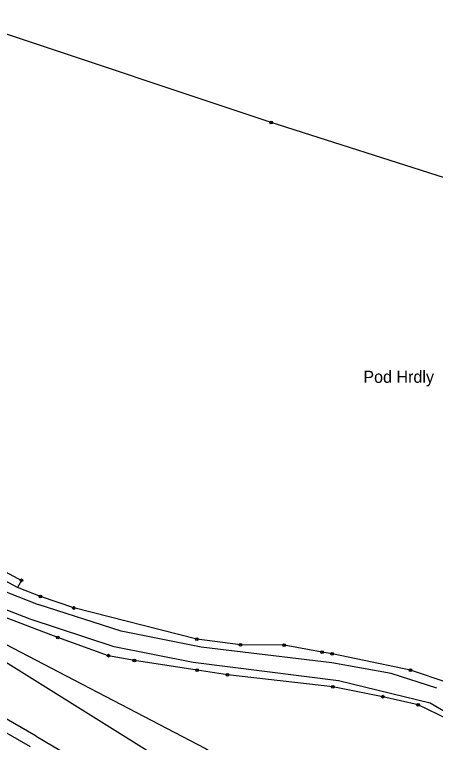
# Model space of a CAD drawing. Extents: x -758582 to -751794, y -998770 to -994350.
# Drawn here: x -754610.6 to -754456.7, y -996434.2 to -996167.7 of the extents above; entities that cross this region are included whole.
import ezdxf

# ---------------------------------------------------------------- set-up
doc = ezdxf.new("R2010")
doc.units = 0
for name, color, linetype in [('Hranice parcel', 7, 'Continuous'), ('Pop  PČ popisy', 7, 'Continuous'), ('Poz předměty', 7, 'Continuous'), ('Vnitřní kresba', 7, 'Continuous'), ('Značky bodu BP', 7, 'Continuous')]:
    doc.layers.add(name, color=color, linetype=linetype)

msp = doc.modelspace()

# ---------------------------------------------------------------- linework, layer by layer
at = {"layer": 'Hranice parcel'}
for points in [[(-754788.86, -996300.01), (-754785.16, -996301.49), (-754719.09, -996332.73), (-754690.11, -996345.48), (-754674.83, -996351.49), (-754634.95, -996361.65), (-754625.47, -996365.55), (-754608.08, -996374.84), (-754609.52, -996377.47)], [(-754609.52, -996377.47), (-754626.61, -996368.32), (-754626.93, -996368.19)], [(-754383.69, -996482.57), (-754386.49, -996481.22), (-754395.83, -996466.38), (-754410.6, -996446.84), (-754437.49, -996420.56), (-754451.97, -996412.36), (-754465.76, -996407.75), (-754494.47, -996401.74), (-754498.09, -996401.1), (-754512, -996398.53), (-754527.95, -996398.42), (-754543.94, -996396.33), (-754588.89, -996384.95), (-754601.1, -996380.73), (-754609.52, -996377.47)], [(-754380.19, -996552.13), (-754385.25, -996519.98), (-754387.72, -996506.25), (-754392.07, -996496.35), (-754394.77, -996491.32), (-754402.71, -996478.9), (-754429.39, -996448.06), (-754441.07, -996434.06), (-754445.75, -996429.16), (-754451.91, -996425.8), (-754462.97, -996420.4), (-754475.9, -996417.42), (-754494.23, -996413.79), (-754532.74, -996409.39), (-754543.79, -996407.71), (-754566.79, -996404.2), (-754576.27, -996402.41), (-754594.78, -996395.73), (-754627.79, -996383.24)], [(-754630.89, -996386.93), (-754622.69, -996393.73), (-754540.76, -996436.36), (-754489.08, -996468.96), (-754461.34, -996488.31), (-754439.14, -996506.23), (-754383.88, -996547.82), (-754380.19, -996552.13)], [(-754376, -996565.84), (-754445.23, -996512.86), (-754489.02, -996482.87), (-754618.93, -996401.76), (-754635.21, -996396.28), (-754637.74, -996394.86)]]:
    msp.add_lwpolyline(points, dxfattribs=at)
at = {"layer": 'Poz předměty'}
for p, q in [((-754516.72, -996207.25), (-754635.04, -996167.71)), ((-754397.31, -996245.46), (-754516.72, -996207.25)), ((-754602.64, -996431.86), (-754633.76, -996414.06)), ((-754604.81, -996435.76), (-754635.9, -996417.94)), ((-754602.64, -996431.86), (-754577.74, -996446.58))]:
    msp.add_line(p, q, dxfattribs=at)
for radius in [0.5, 0.4, 0.3, 0.2, 0.1]:
    msp.add_circle((-754516.72, -996207.25), radius, dxfattribs=at)
at = {"layer": 'Vnitřní kresba'}
for p, q in [((-754626.92, -996373.91), (-754601.91, -996383.66)), ((-754604.92, -996389.09), (-754627.82, -996380.15)), ((-754571.66, -996393.47), (-754601.91, -996383.66)), ((-754574.19, -996399.12), (-754604.92, -996389.09)), ((-754542.31, -996399.24), (-754571.66, -996393.47)), ((-754545.23, -996404.96), (-754574.19, -996399.12)), ((-754494.58, -996405.07), (-754542.31, -996399.24)), ((-754492.12, -996411.58), (-754545.23, -996404.96)), ((-754472.85, -996408.94), (-754494.58, -996405.07)), ((-754456.14, -996414.35), (-754472.85, -996408.94)), ((-754458.57, -996419.79), (-754492.12, -996411.58)), ((-754443.49, -996428.82), (-754458.57, -996419.79))]:
    msp.add_line(p, q, dxfattribs=at)
at = {"layer": 'Značky bodu BP'}
for centre, radius in [((-754608.08, -996374.84), 0.5), ((-754608.08, -996374.84), 0.0303), ((-754601.1, -996380.73), 0.5), ((-754601.1, -996380.73), 0.0303), ((-754588.89, -996384.95), 0.5), ((-754588.89, -996384.95), 0.0303), ((-754594.78, -996395.73), 0.5), ((-754594.78, -996395.73), 0.0303), ((-754543.94, -996396.33), 0.5), ((-754543.94, -996396.33), 0.0303), ((-754527.95, -996398.42), 0.5), ((-754527.95, -996398.42), 0.0303), ((-754512, -996398.53), 0.5), ((-754512, -996398.53), 0.0303), ((-754576.27, -996402.41), 0.5), ((-754576.27, -996402.41), 0.0303), ((-754498.09, -996401.1), 0.5), ((-754498.09, -996401.1), 0.0303), ((-754494.47, -996401.74), 0.5), ((-754494.47, -996401.74), 0.0303), ((-754566.79, -996404.2), 0.5), ((-754566.79, -996404.2), 0.0303), ((-754543.79, -996407.71), 0.5), ((-754543.79, -996407.71), 0.0303), ((-754465.76, -996407.75), 0.5), ((-754465.76, -996407.75), 0.0303), ((-754532.74, -996409.39), 0.5), ((-754532.74, -996409.39), 0.0303), ((-754494.23, -996413.79), 0.5), ((-754494.23, -996413.79), 0.0303), ((-754475.9, -996417.42), 0.5), ((-754475.9, -996417.42), 0.0303), ((-754462.97, -996420.4), 0.5), ((-754462.97, -996420.4), 0.0303)]:
    msp.add_circle(centre, radius, dxfattribs=at)

# ---------------------------------------------------------------- texts
at = {"layer": 'Pop  PČ popisy'}
msp.add_text('Pod Hrdly', height=4.4, dxfattribs=at).set_placement((-754483.04, -996302.52))

doc.saveas('drawing.dxf')
